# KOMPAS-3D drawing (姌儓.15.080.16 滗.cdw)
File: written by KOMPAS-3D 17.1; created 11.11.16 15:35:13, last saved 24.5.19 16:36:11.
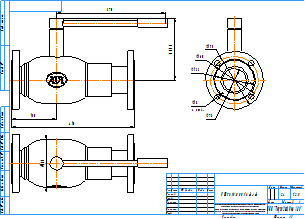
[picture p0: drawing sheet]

Sheet 1: A3, landscape

Title block, sheet 1: name: КШГИ.15.080.16 ф/ф; mass: 24; sheets: 1; organisation: ООО "Торговый дом АДЛ"; sheet format: A3; stored path: C:\Users\kka\KOMPAS_Work\КШП.ГИ\Ду50\КШГИ.15.50.16 ГЧ _ Кран шаровой газовый изолирующий  БИВАЛ Ду50 Ру16  полнопроходной фланцевый Габаритный чертеж.cdw

Views: Вид 1, Проекционный вид 2, Проекционный вид 3
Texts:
  Klimkovich
  ADL
  Рама для чертежей
  Лит-Масса-Масштаб
  Материал-Предприятие
  Масштаб
  Изм.
  Лист
  № докум.
  Подп.
  Дата
  Лит.
  Разраб.
  Пров.
  Т.контр.
  Листов
  Внимание! Данный продукт является объектом авторского права ООО «Торговый Дом АДЛ».
  Запрещается изменение, копирование, распространение
  (в том числе путем копирования на другие сайты и ресурсы в Интернете)
  или любое иное использование информации и объектов без предварительного
  согласия правообладателя (ООО «Торговый Дом АДЛ»).
  Н.контр.
  Утв.
  Изменение
  Номер документа
  Подпись
  Обозначение документа
  Наименование изделия
  Масса изделия по ГОСТ 2.109-73
  Порядковый номер листа
  Общее количество листов в документе
  Характер работы, выполненной лицом, подписавшим документ
  Наименование или индекс предприятия, выпускающего документ
  Инв. № подл.
  Подп. и дата
  Взам. инв. №
  Инв. № дубл.
  Инвентарный номер подлинника по ГОСТ 2.501-68
  Подпись принявшего подлинник в отдел технической документации
  Инвентарный номер подлинника, взамен которого выпущен данный подлинник
  Инвентарный номер дубликата по ГОСТ 2.502-68
  Подпись принявшего дубликат в отдел технической документации
  Справ. №
  Перв. примен.
  Обозначение документа, взамен или на основании которого выпущен данный документ
  Обозначение документа, в котором впервые записан данный документ
  Подпись лица, копировавшего чертеж
  Обозначение формата листа
  !Рама для чертежа
Dimensions and other numbers on the sheet: 370; 207,6; 410; 150; 195; 160; 133; 78; 18; 4 отв.; 159; 1:2,5; 1; 24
